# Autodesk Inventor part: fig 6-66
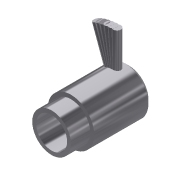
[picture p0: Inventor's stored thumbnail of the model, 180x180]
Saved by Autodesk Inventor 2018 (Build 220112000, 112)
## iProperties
Shininess: 77.0
Angle Display Precision: 2
Document Length Units: 11269
Document Angle Units: 11279
Document Time Units: 11290
Document Mass Units: 11283
Document Length Units Precision: 3
Document Angle Units Precision: 2
Compacted: True
Created: 2001-12
Part Number: fig 6-66
Document SubType Name: Modeling
Designer: Renu Muthoo
Density: 1 g/cm^3
Material: Generic
Appearance: Metal-AL-6061 (Polished)
Density: 0.0
Volumn: 0.0
Area: 0.0
PropertySet Name: Model Information
Control State: 0
Master: False
Checked Out: False
Author: Renu Muthoo
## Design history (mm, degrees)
sketch "Sketch2"
  geometry: L1 (-9.573, -4.327)-(-9.573, -5.327); L2 (-9.573, -5.327)-(-4.573, -5.327); L3 (-4.573, -5.327)-(-4.573, -6.327); L4 (-4.573, -6.327)-(9.427, -6.327); L5 (9.427, -6.327)-(10.427, -5.327); L6 (10.427, -5.327)-(10.427, -4.327); L7 (10.427, -4.327)-(-9.573, -4.327); L8 (-13.687, -0.327)-(14, -0.327)
  constraints: 16 end point, 5 parallel, 1 perpendicular, 1 vertical
  dimensions: "d9" = 20 distance of L6.end L1.start; "d10" = 5 distance of L1.end L2.end; "d11" = 12 diameter of L4 L8; "d12" = 10 diameter of L2 L8; "d13" = 8 diameter of L7 L8; "d14" = 45 deg angle of L5 L4; "d15" = 1 horizontal distance of L5.end L4.end
revolve "Revolution2" sketch "Sketch2" stored, may be unused: angle "d16" = 90 deg
workplane "Work Plane1"
workplane "Work Plane2"
sketch "Sketch3"
  geometry: L1 (-4, 8)-(4, 8) reference; C1 r 1 at (-0.098, 5)
  constraints: 1 centre point
  dimensions: "d18" = 3 distance from line of L1 C1.centre; "d19" = 2 diameter of C1
extrude "Extrusion1" join sketch "Sketch3" distance "d20" = 10; taper "d21" = 0 deg
pattern_circular "Circular Pattern3" dims angle "d29" = 20 deg
body "Solid1"
other parameters: "d17" = -1
